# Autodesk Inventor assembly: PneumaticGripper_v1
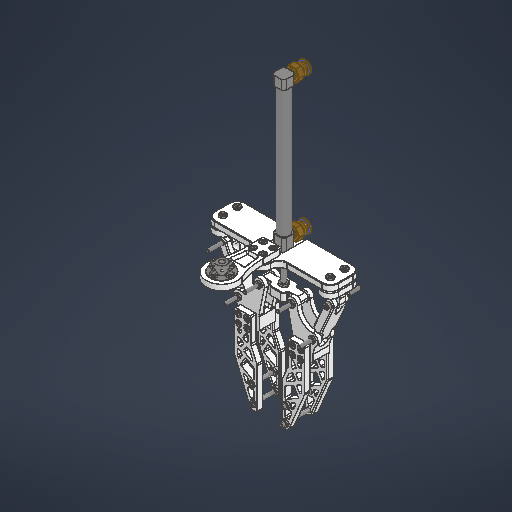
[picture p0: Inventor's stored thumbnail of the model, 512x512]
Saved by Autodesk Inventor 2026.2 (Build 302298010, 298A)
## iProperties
Created: 2026-05
Part Number: PneumaticGripper_v1
Document SubType Name: Assembly
Designer: work
Author: work
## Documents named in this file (16)
- C:\Users\work\Desktop\ARD_v1\ARD_hardware\PneumaticGripper_v1\PneumaticGripper_v1.iam
- C:\Users\work\Desktop\ARD_v1\ARD_hardware\PneumaticGripper_v1\Pneumatic fitting\CDJ2B10_100\CDJ2B10.iam
- C:\Users\work\Desktop\ARD_v1\ARD_hardware\PneumaticGripper_v1\Cylinder fixing parts.ipt
- C:\Users\work\Desktop\ARD_v1\ARD_hardware\PneumaticGripper_v1\rod-fixing parts.ipt
- C:\Users\work\Desktop\ARD_v1\ARD_hardware\PneumaticGripper_v1\Pneumatic fitting\CDJ2B10_100\Rod.ipt
- C:\Users\work\Desktop\ARD_v1\ARD_hardware\PneumaticGripper_v1\Pneumatic fitting\CDJ2B10_100\AS 1474 - M4(1).ipt
- C:\Users\work\Desktop\ARD_v1\ARD_hardware\PneumaticGripper_v1\Bottom Link Parts.ipt
- C:\Users\work\Desktop\ARD_v1\ARD_hardware\PneumaticGripper_v1\Link Support Parts.ipt
- C:\Users\work\Desktop\ARD_v1\ARD_hardware\PneumaticGripper_v1\Link Parts.ipt
- C:\Users\work\Desktop\ARD_v1\ARD_hardware\PneumaticGripper_v1\Tongs_R.ipt
- C:\Users\work\Desktop\ARD_v1\ARD_hardware\PneumaticGripper_v1\Tongs_l.ipt
- C:\Users\work\Desktop\ARD_v1\ARD_hardware\PneumaticGripper_v1\ovject\KS B 1003 - M 3 x 12.ipt
- C:\Users\work\Desktop\ARD_v1\ARD_hardware\PneumaticGripper_v1\ovject\KS B 1003 - M 3 x 30.ipt
- C:\Users\work\Desktop\ARD_v1\ARD_hardware\PneumaticGripper_v1\ovject\JIS B 1181 - A_B M3.ipt
- C:\Users\work\Desktop\ARD_v1\ARD_hardware\PneumaticGripper_v1\Flange Bracket.ipt
- C:\Users\work\Desktop\ARD_v1\ARD_hardware\PneumaticGripper_v1\ovject\flange joint 16pi (5 to 3).ipt
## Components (81 placed, 15 different names)
1. CDJ2B10:1 [sub-assembly] — 각도:1
2. Cylinder fixing parts:1
3. rod-fixing parts:1
4. Rod:1 — 플러쉬:1
5. Flange Bracket:1
6. AS 1474 - M4(1):1 — 각도:2, 플러쉬:1
7. AS 1474 - M4(1):2 — 각도:3
8. Bottom Link Parts:1
9. Bottom Link Parts:2
10. Link Support Parts:1
11. Link Support Parts:2
12. Link Parts:1
13. Link Parts:3
14. Tongs_R:1
15. Tongs_l:1
16. Tongs_R:3
17. Tongs_l:2
18. JIS B 1181 - A_B M3:18
19. JIS B 1181 - A_B M3:19
20. JIS B 1181 - A_B M3:20
21. JIS B 1181 - A_B M3:21
22. JIS B 1181 - A_B M3:22
23. JIS B 1181 - A_B M3:23
24. JIS B 1181 - A_B M3:24
25. JIS B 1181 - A_B M3:25
26. KS B 1003 - M 3 x 12:22
27. KS B 1003 - M 3 x 12:23
28. KS B 1003 - M 3 x 12:24
29. KS B 1003 - M 3 x 12:25
30. KS B 1003 - M 3 x 12:26
31. KS B 1003 - M 3 x 12:27
32. KS B 1003 - M 3 x 12:28
33. KS B 1003 - M 3 x 12:29
34. KS B 1003 - M 3 x 12:1
35. KS B 1003 - M 3 x 12:2
36. KS B 1003 - M 3 x 12:3
37. KS B 1003 - M 3 x 12:4
38. KS B 1003 - M 3 x 12:5
39. KS B 1003 - M 3 x 12:6
40. KS B 1003 - M 3 x 12:7
41. KS B 1003 - M 3 x 12:8
42. KS B 1003 - M 3 x 12:9
43. KS B 1003 - M 3 x 12:11
44. KS B 1003 - M 3 x 12:12
45. KS B 1003 - M 3 x 12:13
46. KS B 1003 - M 3 x 12:14
47. KS B 1003 - M 3 x 12:15
48. KS B 1003 - M 3 x 12:16
49. KS B 1003 - M 3 x 12:17
50. KS B 1003 - M 3 x 12:18
51. KS B 1003 - M 3 x 12:19
52. KS B 1003 - M 3 x 12:20
53. KS B 1003 - M 3 x 12:21
54. KS B 1003 - M 3 x 30:1
55. KS B 1003 - M 3 x 30:2
56. KS B 1003 - M 3 x 30:3
57. flange joint 16pi (5 to 3):1
58. KS B 1003 - M 3 x 30:4
59. KS B 1003 - M 3 x 30:5
60. KS B 1003 - M 3 x 30:6
61. KS B 1003 - M 3 x 30:7
62. KS B 1003 - M 3 x 30:8
63. KS B 1003 - M 3 x 30:9
64. KS B 1003 - M 3 x 30:10
65. JIS B 1181 - A_B M3:1
66. JIS B 1181 - A_B M3:2
67. JIS B 1181 - A_B M3:3
68. JIS B 1181 - A_B M3:4
69. JIS B 1181 - A_B M3:5
70. JIS B 1181 - A_B M3:6
71. JIS B 1181 - A_B M3:7
72. JIS B 1181 - A_B M3:8
73. JIS B 1181 - A_B M3:9
74. JIS B 1181 - A_B M3:10
75. JIS B 1181 - A_B M3:11
76. JIS B 1181 - A_B M3:12
77. JIS B 1181 - A_B M3:13
78. JIS B 1181 - A_B M3:14
79. JIS B 1181 - A_B M3:15
80. JIS B 1181 - A_B M3:16
81. JIS B 1181 - A_B M3:17
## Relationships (4: Angle 3, Flush 1)
- 각도:1 [Angle]: CDJ2B10:1
- 각도:2 [Angle]: AS 1474 - M4(1):1
- 각도:3 [Angle]: AS 1474 - M4(1):2
- 플러쉬:1 [Flush]: Rod:1 ↔ AS 1474 - M4(1):1
